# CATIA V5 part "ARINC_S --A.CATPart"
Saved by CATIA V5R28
Part number: ARINC_SHELL
Revision: --A
Publications: "Logical Termination.1", "Logical Pin.1", "CAVA", "Face_generated(CAVA)", "Axis_generated(CAVA)", "Face_generated(CAVA).1", "CAVB", "Face_generated(CAVB)", "Axis_generated(CAVB)", "Face_generated(CAVB).1", "CAVC", "Face_generated(CAVC)", "Axis_generated(CAVC)", "Face_generated(CAVC).1", "SCP", "Face_generated(SCP)", "Axis_generated(SCP)", "Face_generated(SCP).1", "CaCP", "Face_generated(CaCP)", "Axis_generated(CaCP)", "Edge_generated(CaCP)", "BaCP", "Face_generated(BaCP)", "Axis_generated(BaCP)", "Edge_generated(BaCP)"
Bounding box of the stored display mesh (mm): x 0 to 33.274, y -22.86 to 22.86, z -88.646 to 88.646
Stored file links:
  C:\Users\ajc8720\Documents\BOEING_WORK\0001-2CES\004-AP242\Boeing-Generic_Harness_R3\ARINC_S --A.CATPart
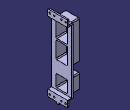
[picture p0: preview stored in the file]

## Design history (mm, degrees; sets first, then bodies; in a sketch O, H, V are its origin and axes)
Parameters
  PartNumber = "BACC66H_S"
  ShellLength = 33.274 mm
  FlangeHeight = 177.292 mm
  FlangeWidth = 45.72 mm
  VerticalCenter = 88.646 mm
  FlangeThickness = 3.175 mm
  FlangeLowerTransition = 15.748 mm
  FlangeUpperTransition = 165.1 mm
  UpperEnclosureTop = 161.417 mm
  UpperEnclosureHeight = 87.0966 mm
  InsertEnclosureWidth = 32.7406 mm
  UpperInserCavitytHorizLocation = 20.955 mm
  CenterInsertCavityHorizLocation = 20.955 mm
  LowerEnclosureHeight = 33.9598 mm
  LowerInsertCavityHorizLocation = 81.915 mm
  UpperClusterInsertCavityHeight = 38.7858 mm
  InsertCavityWidth = 26.8478 mm
  LowerInsertCavityHeight = 28.1178 mm
  DogHeight = 3.302 mm
  DogWidth = 4.7244 mm
  MountingHoleVSpacing = 161.29 mm
  MountingHoleSpacing1 = 16.51 mm
  MountingHoleSpacing2 = 36.2204 mm
  MountingHoleDiameter = 3.7592 mm
  FlangeLocation = 21.082 mm
  FlangeCornerRadius = 1.524 mm
  FlangeWallThickness = 2.54 mm
  ShellEngagingEndRadius = 2.1082 mm
  InsertCavityRadius = 2.1082 mm
  UpperInsertsInterface = 2.794 mm
Set1 "EGFOBody"
  Set2 "CAVOBody"
    Point1 "CAVRPointA": (2.794 {= UpperInsertsInterface}, 0, 50.165)
    Point2 "CAVRPointB": (2.794 {= UpperInsertsInterface}, 0, 8.255)
    Point3 "CAVRPointC": (2.794 {= UpperInsertsInterface}, 0, -52.705)
    Plane1 "CAVCPlane": type OffsetPt, RefPlane face of Pad1 from Sketch1.L6, RefPoint Point1
  Set3 "SCPOBody"
    Point4 "SCPRPoint": (18.923, 0, 0)
    Plane2 "SCPCPlane": type OffsetPt, RefPlane face of Pad1 from Sketch1.L6, RefPoint Point4
  Set4 "CaCPOBody"
    Point5 "CaCPRPoint": (30.099 {= ShellLength-FlangeThickness}, 0, 0)
    Plane3 "CaCPRPlane": type OffsetPt, RefPlane yz-plane, RefPoint Point5
  Set5 "BaCPOBody"
    Point6 "BaCPPoint": (24.257 {= FlangeLocation+FlangeThickness}, 0, 0)
    Plane4 "BaCPPlane": type OffsetPt, RefPlane yz-plane, RefPoint Point6
Set6 "ConstructionGeometry"
  Plane5: type Offset, RefPlane face of Pad1 from Sketch1.L9, Offset 6.35
  Plane6: type Offset, RefPlane xy-plane, Offset 29.21
  Plane7 "DatumCC": type Offset, RefPlane yz-plane, Offset 35.56
  Plane8: type Offset, RefPlane xy-plane, Offset 29.21
  Plane9: type Offset, RefPlane yz-plane, Offset 35.56
Body1 (main body)
  Sketch1 on zx-plane, origin (0, 0, 0), H (-1, 0, 0), V (0, 0, 1)
    line L1 (-24.257, 73.914) -> (-33.274, 73.914)
    line L2 (-33.274, 73.914) -> (-33.274, 88.646)
    line L3 (-33.274, 88.646) -> (-30.099, 88.646)
    line L4 (-30.099, 88.646) -> (-30.099, 76.454)
    line L5 (-30.099, 76.454) -> (-21.082, 76.454)
    line L6 (-21.082, 76.454) -> (-21.082, -72.898)
    line L7 (-21.082, -72.898) -> (-30.099, -72.898)
    point P8 (-30.099, -72.898)
    line L8 (-30.099, -72.898) -> (-30.099, -85.344)
    line L9 (-30.099, -85.344) -> (-33.274, -85.344)
    point P10 (-33.274, -85.344)
    line L10 (-33.274, -85.344) -> (-33.274, -70.358)
    line L11 (-33.274, -70.358) -> (-24.257, -70.358)
    line L12 (-24.257, -70.358) -> (-24.257, 73.914)
    distance L12 L6 = 3.175 {= FlangeThickness}
    length L9 = 3.175 {= FlangeThickness}
    distance L6 V = 21.082 {= FlangeLocation}
    distance L7 L11 = 2.54 {= FlangeWallThickness}
    distance L2 V = 33.274 {= ShellLength}
    distance L3 L9 = 173.99 {= FlangeHeight -DogHeight}
    distance L1 L5 = 2.54 {= FlangeWallThickness}
    distance L9 L7 = 12.446 {= FlangeLowerTransition -DogHeight}
    distance H L9 = 85.344 {= VerticalCenter -DogHeight}
    distance L9 L5 = 161.798 {= FlangeUpperTransition -DogHeight}
    horizontal: L1 H, L3 H, L5 H, L7 H, L9 H, L11 H
    vertical: L2 V, L4 V, L6 V, L8 V, L10 V, L12 V
    coincidence: P8 L4, P10 L2
  Pad1: profile Sketch1, direction (0, 1, 0), length 22.86 {= FlangeWidth /2}, mirrored extent
  Sketch2 on face of Pad1 from Sketch1.L10, origin (33.274, 0, 0), H (0, 1, 0), V (0, 0, 1)
    point P1 (0, -86.995)
    line L1 (2.3622, -85.344) -> (2.3622, -88.646)
    line L2 (2.3622, -88.646) -> (-2.3622, -88.646)
    line L3 (-2.3622, -88.646) -> (-2.3622, -85.344)
    line L4 (-2.3622, -85.344) -> (2.3622, -85.344)
    reference projected line E1 (-41.402, -85.344) -> (41.402, -85.344) from edge [face of Pad1 from Sketch1.L9 | face of Pad1 from Sketch1.L10]
    length L1 = 3.302 {= DogHeight}
    length L2 = 4.7244 {= DogWidth}
    coincidence: P1 V, L4 E1
    vertical: L1 V, L3 V
    horizontal: L2 H, L4 H
    equidistance: L1 L3 P1, L2 L4 P1
  Pad2: profile Sketch2, direction (-1, 0, 0), length 3.175 {= FlangeThickness}
  Sketch3 on face of Pad1 from Sketch1.L6, origin (21.082, 0, 0), H (0, -1, 0), V (0, 0, 1)
    point P1 (0, 29.2227)
    line L1 (16.3703, 70.6628) -> (16.3703, -12.2174)
    line L2 (14.2621, -14.3256) -> (-14.2621, -14.3256)
    line L3 (-16.3703, -12.2174) -> (-16.3703, 70.6628)
    line L4 (-14.2621, 72.771) -> (14.2621, 72.771)
    point P2 (0, -52.6923)
    line L5 (16.3703, -37.8206) -> (16.3703, -67.564)
    line L6 (14.2621, -69.6722) -> (-14.2621, -69.6722)
    line L7 (-16.3703, -67.564) -> (-16.3703, -37.8206)
    line L8 (-14.2621, -35.7124) -> (14.2621, -35.7124)
    reference projected line E1 (2.3622, -88.646) -> (-2.3622, -88.646) from edge [end face of Pad2 | face of Pad2 from Sketch2.L2]
    arc A1 centre (14.2621, 70.6628) radius 2.1082 from (14.2621, 72.771) to (16.3703, 70.6628) cw
    arc A2 centre (-14.2621, 70.6628) radius 2.1082 from (-14.2621, 72.771) to (-16.3703, 70.6628) ccw
    arc A3 centre (-14.2621, -12.2174) radius 2.1082 from (-16.3703, -12.2174) to (-14.2621, -14.3256) ccw
    arc A4 centre (14.2621, -12.2174) radius 2.1082 from (14.2621, -14.3256) to (16.3703, -12.2174) ccw
    arc A5 centre (14.2621, -37.8206) radius 2.1082 from (14.2621, -35.7124) to (16.3703, -37.8206) cw
    arc A6 centre (-14.2621, -37.8206) radius 2.1082 from (-14.2621, -35.7124) to (-16.3703, -37.8206) ccw
    arc A7 centre (-14.2621, -67.564) radius 2.1082 from (-16.3703, -67.564) to (-14.2621, -69.6722) ccw
    arc A8 centre (14.2621, -67.564) radius 2.1082 from (14.2621, -69.6722) to (16.3703, -67.564) ccw
    distance P1 P2 = 81.915 {= LowerInsertCavityHorizLocation}
    distance L1 L3 = 32.7406 {= InsertEnclosureWidth}
    distance L8 L6 = 33.9598 {= LowerEnclosureHeight}
    distance L2 L4 = 87.0966 {= UpperEnclosureHeight}
    distance E1 L4 = 161.417 {= UpperEnclosureTop}
    radius A1 = 2.1082 {= ShellEngagingEndRadius}
    radius A2 = 2.1082 {= InsertCavityRadius}
    radius A3 = 2.1082 {= InsertCavityRadius}
    radius A4 = 2.1082 {= InsertCavityRadius}
    radius A5 = 2.1082 {= ShellEngagingEndRadius}
    radius A6 = 2.1082 {= ShellEngagingEndRadius}
    radius A7 = 2.1082 {= ShellEngagingEndRadius}
    radius A8 = 2.1082 {= InsertCavityRadius}
    coincidence: P1 V, P2 V, L5 L1
    vertical: L1 V, L3 V, L5 V, L7 V
    horizontal: L2 H, L4 H, L6 H, L8 H
    equidistance: L1 L3 P1, L2 L4 P1, L5 L7 P2, L6 L8 P2
    tangency: A1 L4, A1 L1, A2 L4, A2 L3, A3 L3, A3 L2, A4 L2, A4 L1, A5 L8, A5 L5, A6 L8, A6 L7, A7 L7, A7 L6, A8 L6, A8 L5
  Pad3: profile Sketch3, direction (-1, 0, 0), length 21.082 {= FlangeLocation}
  Sketch4 on end face of Pad3, origin (0, 0, 0), H (0, -1, 0), V (0, 0, 1)
    point P1 (0, -52.705)
    line L1 (13.4239, -40.7543) -> (13.4239, -64.6557)
    line L2 (11.3157, -66.7639) -> (-11.3157, -66.7639)
    line L3 (-13.4239, -64.6557) -> (-13.4239, -40.7543)
    line L4 (-11.3157, -38.6461) -> (11.3157, -38.6461)
    point P2 (0, 8.255)
    line L5 (13.4239, 25.5397) -> (13.4239, -9.0297)
    line L6 (11.3157, -11.1379) -> (-11.3157, -11.1379)
    line L7 (-13.4239, -9.0297) -> (-13.4239, 25.5397)
    line L8 (-11.3157, 27.6479) -> (11.3157, 27.6479)
    point P3 (0, 50.165)
    line L9 (13.4239, 67.4497) -> (13.4239, 32.8803)
    line L10 (11.3157, 30.7721) -> (-11.3157, 30.7721)
    line L11 (-13.4239, 32.8803) -> (-13.4239, 67.4497)
    line L12 (-11.3157, 69.5579) -> (11.3157, 69.5579)
    reference intersected line E1 through (0, 29.21) direction (-1, 0) from Plane8
    reference intersected line E2 through (0, 29.21) direction (-1, 0) from Plane8
    reference intersected line E3 through (0, 29.21) direction (-1, 0) from Plane8
    arc A1 centre (11.3157, 67.4497) radius 2.1082 from (11.3157, 69.5579) to (13.4239, 67.4497) cw
    arc A2 centre (-11.3157, 67.4497) radius 2.1082 from (-11.3157, 69.5579) to (-13.4239, 67.4497) ccw
    arc A3 centre (-11.3157, 32.8803) radius 2.1082 from (-13.4239, 32.8803) to (-11.3157, 30.7721) ccw
    arc A4 centre (11.3157, 32.8803) radius 2.1082 from (11.3157, 30.7721) to (13.4239, 32.8803) ccw
    arc A5 centre (11.3157, 25.5397) radius 2.1082 from (11.3157, 27.6479) to (13.4239, 25.5397) cw
    arc A6 centre (-11.3157, 25.5397) radius 2.1082 from (-11.3157, 27.6479) to (-13.4239, 25.5397) ccw
    arc A7 centre (-11.3157, -9.0297) radius 2.1082 from (-13.4239, -9.0297) to (-11.3157, -11.1379) ccw
    arc A8 centre (11.3157, -9.0297) radius 2.1082 from (11.3157, -11.1379) to (13.4239, -9.0297) ccw
    arc A9 centre (11.3157, -40.7543) radius 2.1082 from (11.3157, -38.6461) to (13.4239, -40.7543) cw
    arc A10 centre (-11.3157, -40.7543) radius 2.1082 from (-11.3157, -38.6461) to (-13.4239, -40.7543) ccw
    arc A11 centre (-11.3157, -64.6557) radius 2.1082 from (-13.4239, -64.6557) to (-11.3157, -66.7639) ccw
    arc A12 centre (11.3157, -64.6557) radius 2.1082 from (11.3157, -66.7639) to (13.4239, -64.6557) ccw
    distance L3 L1 = 26.8478 {= InsertCavityWidth}
    distance L2 L4 = 28.1178 {= LowerInsertCavityHeight}
    distance L6 L8 = 38.7858 {= UpperClusterInsertCavityHeight}
    distance L10 L12 = 38.7858 {= UpperClusterInsertCavityHeight}
    distance P3 E1 = 20.955 {= CenterInsertCavityHorizLocation}
    distance P2 E2 = 20.955 {= UpperInserCavitytHorizLocation}
    distance E3 P1 = 81.915 {= LowerInsertCavityHorizLocation}
    radius A1 = 2.1082 {= ShellEngagingEndRadius}
    radius A2 = 2.1082 {= ShellEngagingEndRadius}
    radius A3 = 2.1082 {= InsertCavityRadius}
    radius A4 = 2.1082 {= InsertCavityRadius}
    radius A5 = 2.1082 {= ShellEngagingEndRadius}
    radius A6 = 2.1082 {= InsertCavityRadius}
    radius A7 = 2.1082 {= InsertCavityRadius}
    radius A8 = 2.1082 {= InsertCavityRadius}
    radius A9 = 2.1082 {= ShellEngagingEndRadius}
    radius A10 = 2.1082 {= ShellEngagingEndRadius}
    radius A11 = 2.1082 {= ShellEngagingEndRadius}
    radius A12 = 2.1082 {= InsertCavityRadius}
    distance L9 L11 = 26.8478 {= InsertCavityWidth}
    coincidence: P1 V, P2 V, P3 V, L5 L9
    vertical: L1 V, L3 V, L5 V, L7 V, L9 V, L11 V
    horizontal: L2 H, L4 H, L6 H, L8 H, L10 H, L12 H
    equidistance: L1 L3 P1, L2 L4 P1, L5 L7 P2, L6 L8 P2, L9 L11 P3, L10 L12 P3
    tangency: A1 L12, A1 L9, A2 L12, A2 L11, A3 L11, A3 L10, A4 L10, A4 L9, A5 L8, A5 L5, A6 L8, A6 L7, A7 L7, A7 L6, A8 L6, A8 L5, A9 L4, A9 L1, A10 L4, A10 L3, A11 L3, A11 L2, A12 L2, A12 L1
  Pocket1: profile Sketch4, direction (1, 0, 0), through (limit type 3)
  Fillet1: radius 1.524 {= FlangeCornerRadius}, on edge [face of Pad1 from Sketch1.L9 | end face of Pad1]; edge [start face of Pad1 | face of Pad1 from Sketch1.L9]; edge [start face of Pad1 | face of Pad1 from Sketch1.L3]; edge [face of Pad1 from Sketch1.L3 | end face of Pad1]; edge [face of Pad1 from Sketch1.L5 | end face of Pad1]; edge [start face of Pad1 | face of Pad1 from Sketch1.L5]; edge [start face of Pad1 | face of Pad1 from Sketch1.L7]; edge [face of Pad1 from Sketch1.L7 | end face of Pad1]
  Sketch5 on face of Pad2, origin (30.099, 0, 0), H (0, -1, 0), V (0, 0, 1)
    circle A1 centre (-8.255, -78.994) radius 1.8796
    point P1 (-8.255, -78.994)
    point P2 (8.255, -78.994)
    circle A2 centre (8.255, -78.994) radius 1.8796
    reference intersected line E1 through (0, -78.994) direction (-1, 0) from Plane5
    radius A1 = 1.8796 {= MountingHoleDiameter /2}
    distance V P1 = 8.255 {= MountingHoleSpacing1 /2}
    symmetry: A1 A2 V
    coincidence: P2 E1
  Pocket2: profile Sketch5, direction (-1, 0, 0), through (limit type 6)
  RectPattern1: of Pocket2, direction 1 instances 2, spacing 161.29 {= MountingHoleVSpacing}, along Z axis
  Sketch6 on face of Pad2, origin (33.274, 0, 0), H (0, 1, 0), V (0, 0, 1)
    circle A1 centre (-18.1102, -78.994) radius 1.8796
    point P1 (-18.1102, -78.994)
    circle A2 centre (18.1102, -78.994) radius 1.8796
    point P2 (18.1102, -78.994)
    reference intersected line E1 through (0, -78.994) direction (-1, 0) from Plane5
    distance P1 P2 = 36.2204 {= MountingHoleSpacing2}
    radius A2 = 1.8796 {= MountingHoleDiameter /2}
    radius A1 = 1.8796 {= MountingHoleDiameter /2}
    symmetry: P2 P1 V
    coincidence: P2 E1
  Pocket3: profile Sketch6, direction (-1, 0, 0), through (limit type 6)
  RectPattern2: of Pocket3, direction 1 instances 2, spacing 161.29 {= MountingHoleVSpacing}, along Z axis
Body2 "Male Cherbourg - CaCP"
  Sketch7 "Copy (5) of Sketch.2" on Plane3, origin (30.099, 0, 0), H (0, 1, 0), V (0, 0, 1)
    line L1 (-0.672, 0.762) -> (0.672, 0.762)
    point P1 (-0.672, 0.762)
    point P2 (0.672, 0.762)
    arc A1 centre (0, 0) radius 1.016 from (-1.016, 0) to (1.016, 0) ccw
    point P3 (0, 0)
    point P4 (-1.016, 0)
    point P5 (1.016, 0)
    reference projected point E1 (0, 0)
    arc A2 centre (0, 0) radius 1.016 from (1.016, 0) to (0.672, 0.762) ccw
    point P6 (0, 0)
    point P7 (1.016, 0)
    point P8 (0.672, 0.762)
    arc A3 centre (0, 0) radius 1.016 from (-0.672, 0.762) to (-1.016, 0) ccw
    point P9 (0, 0)
    point P10 (-0.672, 0.762)
    point P11 (-1.016, 0)
    reference projected point E2 (0, 0)
    reference projected point E3 (0, 0)
    length L1 = 1.344
    radius A1 = 1.016
    radius A3 = 1.016
    radius A2 = 1.016
    distance L1 P5 = 0.762
    distance P4 L1 = 0.762
    distance P7 L1 = 0.762
    distance P11 L1 = 0.762
    coincidence: P3 E1, P6 E2, P9 E3, P8 P2, P10 P1
    horizontal: L1 H
  Pad4: profile Sketch7, direction (1, 0, 0), length 0.508, opposite side up to Plane3
Body3 "Male Cherbourg - BaCP"
  Sketch8 "Copy (4) of Sketch.2" on Plane4, origin (24.257, 0, 0), H (0, -1, 0), V (0, 0, 1)
    line L1 (-0.672, 0.762) -> (0.672, 0.762)
    point P1 (-0.672, 0.762)
    point P2 (0.672, 0.762)
    arc A1 centre (0, 0) radius 1.016 from (-1.016, 0) to (1.016, 0) ccw
    point P3 (0, 0)
    point P4 (-1.016, 0)
    point P5 (1.016, 0)
    reference projected point E1 (0, 0)
    arc A2 centre (0, 0) radius 1.016 from (1.016, 0) to (0.672, 0.762) ccw
    point P6 (0, 0)
    point P7 (1.016, 0)
    point P8 (0.672, 0.762)
    arc A3 centre (0, 0) radius 1.016 from (-0.672, 0.762) to (-1.016, 0) ccw
    point P9 (0, 0)
    point P10 (-0.672, 0.762)
    point P11 (-1.016, 0)
    reference projected point E2 (0, 0)
    reference projected point E3 (0, 0)
    length L1 = 1.344
    radius A1 = 1.016
    radius A3 = 1.016
    radius A2 = 1.016
    distance L1 P5 = 0.762
    distance P4 L1 = 0.762
    distance P7 L1 = 0.762
    distance P11 L1 = 0.762
    coincidence: P3 E1, P6 E2, P9 E3, P8 P2, P10 P1
    horizontal: L1 H
  Pad5: profile Sketch8, direction (-1, 0, 0), length 0.508, opposite side up to Plane4
Body4 "Male Cherbourg - SCP"
  Sketch9 "Copy (3) of Sketch.2" on Plane2, origin (18.923, 0, 0), H (0, 1, 0), V (0, 0, 1)
    line L1 (-0.672, 0.762) -> (0.672, 0.762)
    point P1 (-0.672, 0.762)
    point P2 (0.672, 0.762)
    arc A1 centre (0, 0) radius 1.016 from (-1.016, 0) to (1.016, 0) ccw
    point P3 (0, 0)
    point P4 (-1.016, 0)
    point P5 (1.016, 0)
    reference projected point E1 (0, 0)
    arc A2 centre (0, 0) radius 1.016 from (1.016, 0) to (0.672, 0.762) ccw
    point P6 (0, 0)
    point P7 (1.016, 0)
    point P8 (0.672, 0.762)
    arc A3 centre (0, 0) radius 1.016 from (-0.672, 0.762) to (-1.016, 0) ccw
    point P9 (0, 0)
    point P10 (-0.672, 0.762)
    point P11 (-1.016, 0)
    reference projected point E2 (0, 0)
    reference projected point E3 (0, 0)
    length L1 = 1.344
    radius A1 = 1.016
    radius A3 = 1.016
    radius A2 = 1.016
    distance L1 P5 = 0.762
    distance P4 L1 = 0.762
    distance P7 L1 = 0.762
    distance P11 L1 = 0.762
    coincidence: P3 E1, P6 E2, P9 E3, P8 P2, P10 P1
    horizontal: L1 H
  Pad6: profile Sketch9, direction (1, 0, 0), length 0.508, opposite side up to Plane2
Body5 "Female Cherbourg - CAVC"
  Sketch10 "Copy (2) of Sketch.1" on Plane1, origin (2.794, 0, -52.705), H (0, 1, 0), V (0, 0, 1)
    circle A1 centre (0, 0) radius 1.27
    point P1 (0, 0)
    reference projected point E1 (0, 0) from Point3
    radius A1 = 1.27
    coincidence: P1 E1
  Pad7: profile Sketch10, direction (1, 0, 0), length 0.254, opposite side length 0.254
  Sketch11 "Copy (2) of Sketch.2" on Plane1, origin (2.794, 0, -52.705), H (0, 1, 0), V (0, 0, 1)
    line L1 (-0.672, 0.762) -> (0.672, 0.762)
    point P1 (-0.672, 0.762)
    point P2 (0.672, 0.762)
    arc A1 centre (0, 0) radius 1.016 from (-1.016, 0) to (1.016, 0) ccw
    point P3 (0, 0)
    point P4 (-1.016, 0)
    point P5 (1.016, 0)
    reference projected point E1 (0, 0) from Point3
    arc A2 centre (0, 0) radius 1.016 from (1.016, 0) to (0.672, 0.762) ccw
    point P6 (0, 0)
    point P7 (1.016, 0)
    point P8 (0.672, 0.762)
    arc A3 centre (0, 0) radius 1.016 from (-0.672, 0.762) to (-1.016, 0) ccw
    point P9 (0, 0)
    point P10 (-0.672, 0.762)
    point P11 (-1.016, 0)
    reference projected point E2 (0, 0) from Point3
    reference projected point E3 (0, 0) from Point3
    length L1 = 1.344
    radius A1 = 1.016
    radius A3 = 1.016
    radius A2 = 1.016
    distance L1 P5 = 0.762
    distance P4 L1 = 0.762
    distance P7 L1 = 0.762
    distance P11 L1 = 0.762
    coincidence: P3 E1, P6 E2, P9 E3, P8 P2, P10 P1
    horizontal: L1 H
  Pocket4: profile Sketch11, direction (1, 0, 0), through (limit type 6)
Body6 "Female Cherbourg - CAVB"
  Sketch12 "Copy of Sketch.1" on Plane1, origin (2.794, 0, 8.255), H (0, 1, 0), V (0, 0, 1)
    circle A1 centre (0, 0) radius 1.27
    point P1 (0, 0)
    reference projected point E1 (0, 0) from Point2
    radius A1 = 1.27
    coincidence: P1 E1
  Pad8: profile Sketch12, direction (1, 0, 0), length 0.254, opposite side length 0.254
  Sketch13 "Copy of Sketch.2" on Plane1, origin (2.794, 0, 8.255), H (0, 1, 0), V (0, 0, 1)
    line L1 (-0.672, 0.762) -> (0.672, 0.762)
    point P1 (-0.672, 0.762)
    point P2 (0.672, 0.762)
    arc A1 centre (0, 0) radius 1.016 from (-1.016, 0) to (1.016, 0) ccw
    point P3 (0, 0)
    point P4 (-1.016, 0)
    point P5 (1.016, 0)
    reference projected point E1 (0, 0) from Point2
    arc A2 centre (0, 0) radius 1.016 from (1.016, 0) to (0.672, 0.762) ccw
    point P6 (0, 0)
    point P7 (1.016, 0)
    point P8 (0.672, 0.762)
    arc A3 centre (0, 0) radius 1.016 from (-0.672, 0.762) to (-1.016, 0) ccw
    point P9 (0, 0)
    point P10 (-0.672, 0.762)
    point P11 (-1.016, 0)
    reference projected point E2 (0, 0) from Point2
    reference projected point E3 (0, 0) from Point2
    length L1 = 1.344
    radius A1 = 1.016
    radius A3 = 1.016
    radius A2 = 1.016
    distance L1 P5 = 0.762
    distance P4 L1 = 0.762
    distance P7 L1 = 0.762
    distance P11 L1 = 0.762
    coincidence: P3 E1, P6 E2, P9 E3, P8 P2, P10 P1
    horizontal: L1 H
  Pocket5: profile Sketch13, direction (1, 0, 0), through (limit type 6)
Body7 "Female Cherbourg - CAVA"
  Sketch14 "Sketch.1" on Plane1, origin (2.794, 0, 50.165), H (0, 1, 0), V (0, 0, 1)
    circle A1 centre (0, 0) radius 1.27
    point P1 (0, 0)
    reference projected point E1 (0, 0) from Point1
    radius A1 = 1.27
    coincidence: P1 E1
  Pad9: profile Sketch14, direction (1, 0, 0), length 0.254, opposite side length 0.254
  Sketch15 "Sketch.2" on Plane1, origin (2.794, 0, 50.165), H (0, 1, 0), V (0, 0, 1)
    line L1 (-0.672, 0.762) -> (0.672, 0.762)
    point P1 (-0.672, 0.762)
    point P2 (0.672, 0.762)
    arc A1 centre (0, 0) radius 1.016 from (-1.016, 0) to (1.016, 0) ccw
    point P3 (0, 0)
    point P4 (-1.016, 0)
    point P5 (1.016, 0)
    reference projected point E1 (0, 0) from Point1
    arc A2 centre (0, 0) radius 1.016 from (1.016, 0) to (0.672, 0.762) ccw
    point P6 (0, 0)
    point P7 (1.016, 0)
    point P8 (0.672, 0.762)
    arc A3 centre (0, 0) radius 1.016 from (-0.672, 0.762) to (-1.016, 0) ccw
    point P9 (0, 0)
    point P10 (-0.672, 0.762)
    point P11 (-1.016, 0)
    reference projected point E2 (0, 0) from Point1
    reference projected point E3 (0, 0) from Point1
    length L1 = 1.344
    radius A1 = 1.016
    radius A3 = 1.016
    radius A2 = 1.016
    distance L1 P5 = 0.762
    distance P4 L1 = 0.762
    distance P7 L1 = 0.762
    distance P11 L1 = 0.762
    coincidence: P3 E1, P6 E2, P9 E3, P8 P2, P10 P1
    horizontal: L1 H
  Pocket6: profile Sketch15, direction (1, 0, 0), through (limit type 6)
